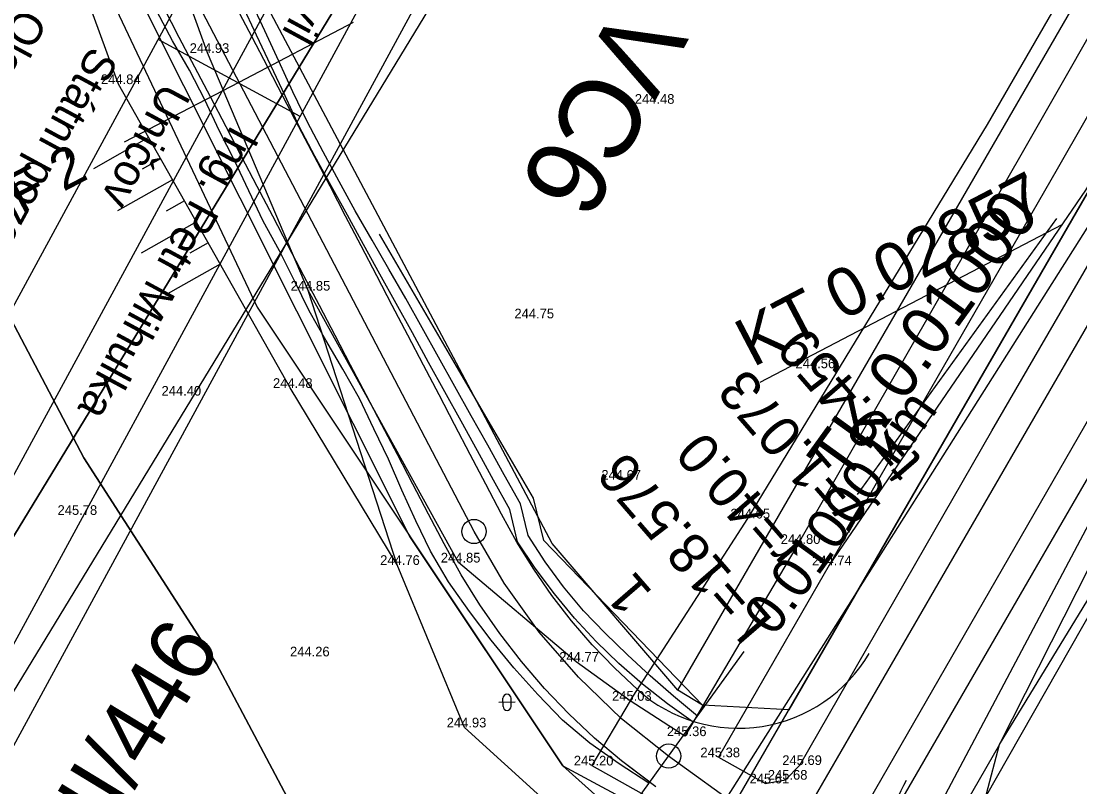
# Model space of a CAD drawing. Extents: x -555887 to -552101, y -1100251 to -1096546.
# Drawn here: x -554080.2 to -554014.6, y -1097317.8 to -1097270.3 of the extents above; entities that cross this region are included whole.
import ezdxf

# ---------------------------------------------------------------- set-up
doc = ezdxf.new("R2010")
doc.units = 0
for name, color, linetype in [('PARCELY_cesty', 7, 'Continuous'), ('PARCELY_silnice', 7, 'Continuous'), ('PARCELY_VHO', 7, 'Continuous'), ('POLYGONY_rozšíření', 7, 'Continuous'), ('POLYGONY_SITUACE_PF', 7, 'Continuous'), ('POLYGONY_SITUACE_PF_POPISY', 7, 'Continuous'), ('POLYGONY_SITUACE_PO', 7, 'Continuous'), ('ROZHLED_parcela_cesty', 7, 'Continuous'), ('ROZHLED_ram_legenda_1', 7, 'Continuous'), ('ROZHLED_ram_legenda_2', 7, 'Continuous'), ('ROZHLED_trojuhelniky_1', 7, 'Continuous'), ('ROZHLED_trojuhelniky_2', 7, 'Continuous'), ('Výškopis', 7, 'Continuous'), ('ZSST', 7, 'Continuous'), ('zájem', 7, 'Continuous')]:
    doc.layers.add(name, color=color, linetype=linetype)

msp = doc.modelspace()

# ---------------------------------------------------------------- linework, layer by layer
for p, q in [((-554034.416, -1097292.667), (-554015.721, -1097282.901)), ((-554028.391, -1097299.626), (-554016.05, -1097282.521))]:
    msp.add_line(p, q)
at = {"layer": 'PARCELY_cesty'}
for points in [[(-554039.52, -1097311.76), (-554047.31, -1097302.68), (-554067.59, -1097264.38), (-554070.02, -1097259.26), (-554071.42, -1097254.1), (-554072.18, -1097247.42), (-554073.837, -1097234.701), (-554074.64, -1097229.027), (-554076.858, -1097220.767), (-554079.626, -1097213.575), (-554082.86, -1097207.774), (-554099.501, -1097180.734), (-554106.075, -1097169.208), (-554111.955, -1097157.47), (-554115.449, -1097149.447), (-554124.686, -1097127.011)], [(-554038.74, -1097323.54), (-554046.65, -1097316.45), (-554056.115, -1097302.24), (-554073.622, -1097267.292), (-554075.994, -1097261.695), (-554077.187, -1097257.67), (-554078.248, -1097251.684), (-554079.797, -1097235.406), (-554080.53, -1097230.23), (-554082.571, -1097222.628), (-554085.074, -1097216.125), (-554088.037, -1097210.809), (-554104.663, -1097183.794), (-554111.367, -1097172.04), (-554117.392, -1097160.013), (-554120.974, -1097151.787), (-554130.309, -1097129.113)]]:
    msp.add_lwpolyline(points, dxfattribs=at)
at = {"layer": 'PARCELY_silnice'}
for points in [[(-553861.3, -1097003.46), (-553858.48, -1097005.9), (-553845.75, -1096975.04), (-553836.44, -1096945.29), (-553831.55, -1096945.97), (-553834.33, -1096958.81), (-553843.04, -1096981.51), (-553856.4, -1097007.66), (-554032.65, -1097312.99), (-554038, -1097312.7), (-554039.52, -1097311.76)], [(-553831.55, -1096945.97), (-553822.14, -1096946.52), (-553820.19, -1096947.25), (-553823.19, -1096962.08), (-553832.13, -1096986.8), (-553848.04, -1097015.24), (-554028.81, -1097333.03), (-554038.74, -1097323.54), (-553856.4, -1097007.66), (-553843.04, -1096981.51), (-553834.33, -1096958.81)]]:
    msp.add_lwpolyline(points, close=True, dxfattribs=at)
at = {"layer": 'PARCELY_VHO'}
for points in [[(-553890.36, -1097670.23), (-553902.88, -1097642.35), (-553905.32, -1097611.67), (-553898.3, -1097524.98), (-553901.53, -1097506.94), (-553991.85, -1097382.83), (-554027.72, -1097360.75), (-554038.93, -1097345.45), (-554044.87, -1097337.64), (-554055.91, -1097333.12), (-554068.1, -1097310.12), (-554076.3, -1097297.37), (-554083.64, -1097283.44), (-554094.93, -1097256.14), (-554100.02, -1097244.94), (-554114.01, -1097204.34), (-554130.46, -1097180.06), (-554159.17, -1097101.34)], [(-554141.5, -1097107.04), (-554133.09, -1097133.96), (-554115.31, -1097177.28), (-554094.19, -1097204.11), (-554083.82, -1097222.99), (-554081.04, -1097249.03), (-554076.85, -1097264.17), (-554065.58, -1097288.03), (-554046.65, -1097316.45), (-554038.74, -1097323.54), (-554028.81, -1097333.03), (-554018.781, -1097341.326), (-554015.89, -1097351.24), (-554008.949, -1097355.38), (-553990.01, -1097365.499), (-553983.508, -1097370.361), (-553977.642, -1097376.021), (-553888.1, -1097498.254), (-553882.924, -1097507.258), (-553879.092, -1097522.388), (-553886.84, -1097615.05), (-553883.68, -1097641.57), (-553876.67, -1097669.5)]]:
    msp.add_lwpolyline(points, dxfattribs=at)
at = {"layer": 'POLYGONY_rozšíření'}
for centre, radius, start, end in [((-554035.765, -1097304.731), 9.388, 228.32637, 329.58502), ((-554017.599, -1097321.883), 9, 149.8415, 220.91473)]:
    msp.add_arc(centre, radius, start, end, dxfattribs=at)
at = {"layer": 'POLYGONY_SITUACE_PF'}
for p, q in [((-554066.694, -1097274.074), (-554059.604, -1097270.37)), ((-554073.785, -1097277.778), (-554066.694, -1097274.074)), ((-554040.095, -1097315.845), (-554035.414, -1097309.357)), ((-554044.776, -1097322.332), (-554040.095, -1097315.845))]:
    msp.add_line(p, q, dxfattribs=at)
at = {"layer": 'POLYGONY_SITUACE_PO'}
for p, q in [((-554052.143, -1097301.928), (-554070.907, -1097266.01)), ((-554065.621, -1097271.163), (-554066.506, -1097269.275)), ((-554065.107, -1097270.894), (-554065.979, -1097268.999)), ((-554070.819, -1097271.527), (-554071.782, -1097269.68)), ((-554070.396, -1097271.307), (-554071.361, -1097269.46)), ((-554065.886, -1097271.301), (-554066.851, -1097269.455)), ((-554064.735, -1097273.05), (-554065.621, -1097271.163)), ((-554064.235, -1097272.789), (-554065.107, -1097270.894)), ((-554069.767, -1097273.328), (-554070.819, -1097271.527)), ((-554069.432, -1097273.153), (-554070.396, -1097271.307)), ((-554064.922, -1097273.148), (-554065.886, -1097271.301)), ((-554068.467, -1097275), (-554069.432, -1097273.153)), ((-554063.957, -1097274.994), (-554064.922, -1097273.148)), ((-554063.85, -1097274.938), (-554064.735, -1097273.05)), ((-554063.358, -1097274.681), (-554064.235, -1097272.789)), ((-554068.816, -1097275.182), (-554069.767, -1097273.328)), ((-554067.926, -1097277.068), (-554068.816, -1097275.182)), ((-554067.502, -1097276.846), (-554068.467, -1097275)), ((-554062.992, -1097276.841), (-554063.957, -1097274.994)), ((-554062.964, -1097276.826), (-554063.85, -1097274.938)), ((-554062.458, -1097276.562), (-554063.358, -1097274.681)), ((-554066.983, -1097278.926), (-554067.926, -1097277.068)), ((-554066.538, -1097278.693), (-554067.502, -1097276.846)), ((-554062.028, -1097278.687), (-554062.992, -1097276.841)), ((-554062.001, -1097278.673), (-554062.964, -1097276.826)), ((-554061.494, -1097278.408), (-554062.458, -1097276.562)), ((-554060.486, -1097280.232), (-554061.494, -1097278.408)), ((-554066.086, -1097280.808), (-554066.983, -1097278.926)), ((-554065.573, -1097280.539), (-554066.538, -1097278.693)), ((-554061.063, -1097280.534), (-554062.028, -1097278.687)), ((-554060.994, -1097280.498), (-554062.001, -1097278.673)), ((-554059.495, -1097282.065), (-554060.486, -1097280.232)), ((-554065.211, -1097282.701), (-554066.086, -1097280.808)), ((-554064.608, -1097282.386), (-554065.573, -1097280.539)), ((-554060.098, -1097282.38), (-554061.063, -1097280.534)), ((-554059.988, -1097282.323), (-554060.994, -1097280.498)), ((-554063.644, -1097284.233), (-554064.608, -1097282.386)), ((-554059.134, -1097284.227), (-554060.098, -1097282.38)), ((-554058.981, -1097284.147), (-554059.988, -1097282.323)), ((-554058.447, -1097283.868), (-554059.495, -1097282.065)), ((-554064.201, -1097284.524), (-554065.211, -1097282.701)), ((-554062.679, -1097286.079), (-554063.644, -1097284.233)), ((-554058.169, -1097286.074), (-554059.134, -1097284.227)), ((-554057.975, -1097285.972), (-554058.981, -1097284.147)), ((-554057.412, -1097285.678), (-554058.447, -1097283.868)), ((-554063.271, -1097286.388), (-554064.201, -1097284.524)), ((-554056.377, -1097287.488), (-554057.412, -1097285.678)), ((-554061.715, -1097287.926), (-554062.679, -1097286.079)), ((-554057.205, -1097287.92), (-554058.169, -1097286.074)), ((-554056.969, -1097287.797), (-554057.975, -1097285.972)), ((-554062.358, -1097288.262), (-554063.271, -1097286.388)), ((-554055.353, -1097289.303), (-554056.377, -1097287.488)), ((-554061.312, -1097290.066), (-554062.358, -1097288.262)), ((-554060.75, -1097289.772), (-554061.715, -1097287.926)), ((-554056.24, -1097289.767), (-554057.205, -1097287.92)), ((-554055.962, -1097289.622), (-554056.969, -1097287.797)), ((-554054.956, -1097291.446), (-554055.962, -1097289.622)), ((-554054.342, -1097291.126), (-554055.353, -1097289.303)), ((-554060.267, -1097291.87), (-554061.312, -1097290.066)), ((-554059.785, -1097291.619), (-554060.75, -1097289.772)), ((-554055.275, -1097291.613), (-554056.24, -1097289.767)), ((-554053.949, -1097293.271), (-554054.956, -1097291.446)), ((-554053.331, -1097292.948), (-554054.342, -1097291.126)), ((-554059.23, -1097293.679), (-554060.267, -1097291.87)), ((-554058.821, -1097293.465), (-554059.785, -1097291.619)), ((-554054.311, -1097293.46), (-554055.275, -1097291.613)), ((-554057.856, -1097295.312), (-554058.821, -1097293.465)), ((-554053.346, -1097295.306), (-554054.311, -1097293.46)), ((-554052.943, -1097295.096), (-554053.949, -1097293.271)), ((-554052.314, -1097294.767), (-554053.331, -1097292.948)), ((-554058.34, -1097295.564), (-554059.23, -1097293.679)), ((-554051.29, -1097296.583), (-554052.314, -1097294.767)), ((-554056.891, -1097297.158), (-554057.856, -1097295.312)), ((-554052.381, -1097297.153), (-554053.346, -1097295.306)), ((-554051.937, -1097296.921), (-554052.943, -1097295.096)), ((-554057.446, -1097297.448), (-554058.34, -1097295.564)), ((-554050.285, -1097298.408), (-554051.29, -1097296.583)), ((-554056.614, -1097299.364), (-554057.446, -1097297.448)), ((-554055.927, -1097299.005), (-554056.891, -1097297.158)), ((-554051.417, -1097298.999), (-554052.381, -1097297.153)), ((-554050.93, -1097298.745), (-554051.937, -1097296.921)), ((-554049.924, -1097300.57), (-554050.93, -1097298.745)), ((-554049.259, -1097300.223), (-554050.285, -1097298.408)), ((-554055.744, -1097301.26), (-554056.614, -1097299.364)), ((-554054.962, -1097300.852), (-554055.927, -1097299.005)), ((-554050.452, -1097300.846), (-554051.417, -1097298.999)), ((-554049.457, -1097302.566), (-554049.924, -1097300.57)), ((-554048.795, -1097302.179), (-554049.259, -1097300.223)), ((-554054.837, -1097303.137), (-554055.744, -1097301.26)), ((-554053.997, -1097302.698), (-554054.962, -1097300.852)), ((-554049.495, -1097302.588), (-554050.452, -1097300.846)), ((-554050.273, -1097305.136), (-554052.143, -1097301.928)), ((-554052.948, -1097304.607), (-554053.997, -1097302.698)), ((-554048.448, -1097304.267), (-554049.495, -1097302.588)), ((-554048.353, -1097304.205), (-554049.457, -1097302.566)), ((-554047.733, -1097303.798), (-554048.795, -1097302.179)), ((-554053.716, -1097305.056), (-554054.837, -1097303.137)), ((-554046.6, -1097305.365), (-554047.733, -1097303.798)), ((-554051.791, -1097306.463), (-554052.948, -1097304.607)), ((-554047.316, -1097305.89), (-554048.448, -1097304.267)), ((-554047.168, -1097305.782), (-554048.353, -1097304.205)), ((-554052.426, -1097306.88), (-554053.716, -1097305.056)), ((-554048.113, -1097308.157), (-554050.273, -1097305.136)), ((-554046.108, -1097307.458), (-554047.316, -1097305.89)), ((-554045.913, -1097307.298), (-554047.168, -1097305.782)), ((-554045.358, -1097306.845), (-554046.6, -1097305.365)), ((-554050.54, -1097308.257), (-554051.791, -1097306.463)), ((-554051.088, -1097308.659), (-554052.426, -1097306.88)), ((-554044.581, -1097308.743), (-554045.913, -1097307.298)), ((-554044.022, -1097308.236), (-554045.358, -1097306.845)), ((-554044.82, -1097308.96), (-554046.108, -1097307.458)), ((-554049.205, -1097309.99), (-554050.54, -1097308.257)), ((-554045.682, -1097310.965), (-554048.113, -1097308.157)), ((-554042.636, -1097309.568), (-554044.022, -1097308.236)), ((-554049.676, -1097310.375), (-554051.088, -1097308.659)), ((-554043.447, -1097310.385), (-554044.82, -1097308.96)), ((-554043.171, -1097310.107), (-554044.581, -1097308.743)), ((-554041.225, -1097310.867), (-554042.636, -1097309.568)), ((-554048.2, -1097312.031), (-554049.676, -1097310.375)), ((-554047.781, -1097311.65), (-554049.205, -1097309.99)), ((-554042.008, -1097311.743), (-554043.447, -1097310.385)), ((-554041.701, -1097311.399), (-554043.171, -1097310.107)), ((-554043.001, -1097313.535), (-554045.682, -1097310.965)), ((-554039.786, -1097312.137), (-554041.225, -1097310.867)), ((-554046.264, -1097313.225), (-554047.781, -1097311.65)), ((-554042.008, -1097311.743), (-554042.008, -1097311.743)), ((-554042.008, -1097311.743), (-554042.008, -1097311.743)), ((-554040.165, -1097312.608), (-554041.701, -1097311.399)), ((-554046.661, -1097313.626), (-554048.2, -1097312.031)), ((-554038.313, -1097313.375), (-554039.786, -1097312.137)), ((-554044.673, -1097314.726), (-554046.264, -1097313.225)), ((-554038.573, -1097313.736), (-554040.165, -1097312.608)), ((-554044.967, -1097315.056), (-554046.661, -1097313.626)), ((-554040.093, -1097315.846), (-554043.001, -1097313.535)), ((-554043.159, -1097316.332), (-554044.967, -1097315.056)), ((-554043.003, -1097316.139), (-554044.673, -1097314.726)), ((-554043.003, -1097316.139), (-554044.673, -1097314.726)), ((-554031.985, -1097321.695), (-554040.093, -1097315.846)), ((-554041.31, -1097317.528), (-554043.159, -1097316.332)), ((-554041.265, -1097317.466), (-554043.003, -1097316.139)), ((-554040.89, -1097317.753), (-554043.003, -1097316.139))]:
    msp.add_line(p, q, dxfattribs=at)
for centre in [(-554052.143, -1097301.928), (-554040.093, -1097315.846)]:
    msp.add_circle(centre, 0.75, dxfattribs=at)
at = {"layer": 'ROZHLED_parcela_cesty'}
msp.add_lwpolyline([(-554065.58, -1097288.03), (-554046.65, -1097316.45), (-554041.23, -1097319.36), (-554038.83, -1097321.49), (-554038.74, -1097323.54), (-554032.65, -1097312.99), (-554038, -1097312.7), (-554047.82, -1097302.49), (-554048.47, -1097299.87), (-554057.99, -1097283.5)], dxfattribs=at)
at = {"layer": 'ROZHLED_ram_legenda_1'}
for p, q in [((-554063.6, -1097256.492), (-554120.836, -1097361.963)), ((-554059.206, -1097258.877), (-554116.441, -1097364.348)), ((-554062.92, -1097276.204), (-554071.709, -1097271.434))]:
    msp.add_line(p, q, dxfattribs=at)
for points in [[(-554050.744, -1097260.056), (-554139.459, -1097423.536), (-554197.468, -1097392.056), (-554108.752, -1097228.576)], [(-554054.811, -1097261.262), (-554140.665, -1097419.468), (-554193.4, -1097390.85), (-554107.547, -1097232.644)]]:
    msp.add_lwpolyline(points, close=True, dxfattribs=at)
at = {"layer": 'ROZHLED_ram_legenda_2'}
msp.add_lwpolyline([(-553994.764, -1097161.002), (-553815.355, -1097270.146), (-553969.717, -1097523.882), (-554149.126, -1097414.737)], close=True, dxfattribs=at)
msp.add_lwpolyline([(-553994.764, -1097161.002), (-553815.355, -1097270.146), (-553969.717, -1097523.882), (-554149.126, -1097414.737)], close=True, dxfattribs=at)
for points in [[(-554149.126, -1097414.737), (-553969.717, -1097523.882), (-553815.355, -1097270.146), (-553994.764, -1097161.002), (-554149.126, -1097414.737)], [(-553822.226, -1097271.819), (-553971.39, -1097517.011), (-554142.255, -1097413.064), (-553993.091, -1097167.872), (-553822.226, -1097271.819)], [(-553822.226, -1097271.819), (-553971.39, -1097517.011), (-554142.255, -1097413.064), (-553993.091, -1097167.872), (-553822.226, -1097271.819)]]:
    msp.add_lwpolyline(points, dxfattribs=at)
at = {"layer": 'ROZHLED_trojuhelniky_1'}
for p in [(-554036.491, -1097318.429), (-554032.67, -1097321.18)]:
    msp.add_line(p, (-553972.591, -1097217.302), dxfattribs=at)
at = {"layer": 'ROZHLED_trojuhelniky_2'}
for p in [(-554030.46, -1097323.44), (-554027.516, -1097326.853)]:
    msp.add_line(p, (-553970.641, -1097219.412), dxfattribs=at)
at = {"layer": 'ZSST'}
for p, q in [((-554072.294, -1097277.517), (-554075.705, -1097279.446)), ((-554071.556, -1097278.823), (-554072.691, -1097279.465)), ((-554070.817, -1097280.128), (-554074.228, -1097282.057)), ((-554070.079, -1097281.434), (-554071.215, -1097282.076)), ((-554069.34, -1097282.739), (-554072.751, -1097284.669)), ((-554068.602, -1097284.045), (-554069.738, -1097284.688)), ((-554067.863, -1097285.351), (-554071.274, -1097287.28)), ((-554049.598, -1097312.513), (-554050.598, -1097312.518)), ((-554050.347, -1097312.767), (-554050.35, -1097312.267)), ((-554049.847, -1097312.764), (-554049.85, -1097312.264))]:
    msp.add_line(p, q, dxfattribs=at)
for points in [[(-554042.48, -1097312.42), (-554035.18, -1097301.12), (-554020.35, -1097276.71), (-554001.25, -1097243.62), (-553975.55, -1097199.35), (-553927.26, -1097115.35), (-553902.63, -1097072.54), (-553878.35, -1097029.34), (-553858.27, -1096995.26), (-553851.54, -1096982.63), (-553845.34, -1096967.24), (-553838.37, -1096941.91), (-553834.5, -1096923.22)], [(-553831.64, -1096923.82), (-553835.69, -1096943.09), (-553842.4, -1096966.86), (-553850.34, -1096985.69), (-553856.05, -1096996.17), (-553876.09, -1097031.09), (-553900.82, -1097073.95), (-553925.65, -1097117.01), (-553973.36, -1097200.46), (-553998.81, -1097244.48), (-554018.03, -1097278.18), (-554032.06, -1097302.7), (-554039.09, -1097314.61), (-554042.48, -1097312.42), (-554044.85, -1097316.43), (-554041.28, -1097318.43), (-554043.66, -1097322.75), (-554050.44, -1097334.64), (-554051.91, -1097337.2)], [(-553818.18, -1096926.71), (-553821.78, -1096945.09), (-553822.5, -1096948.29), (-553824.54, -1096956.94), (-553827.64, -1096967.4), (-553833.07, -1096981.13), (-553839.89, -1096995.89), (-553855.52, -1097024.97), (-553869.86, -1097050.06), (-553885.29, -1097076.39), (-553900.2, -1097101.88), (-553913.69, -1097125.22), (-553931.8, -1097156.33), (-553935.29, -1097162.25), (-553959.78, -1097204.54), (-553977.15, -1097234.71), (-553995.37, -1097266.5), (-554014.37, -1097299.01), (-554027.49, -1097321.67), (-554032.14, -1097329.71), (-554046.52, -1097353.89)], [(-554056.9, -1097304), (-554063.52, -1097293.03), (-554074.17, -1097274.2), (-554078.71, -1097261.75), (-554082.34, -1097246.77), (-554082.1, -1097236.17), (-554084.78, -1097223.3), (-554095.29, -1097205.66), (-554110.17, -1097187.25), (-554117, -1097177.37), (-554121.76, -1097162.68), (-554126.27, -1097148.83), (-554134.49, -1097136.49), (-554138.97, -1097119.53)], [(-553924.99, -1097120.68), (-553971.37, -1097201.71), (-553996.85, -1097245.92), (-554016.03, -1097279.48), (-554030.15, -1097304.02), (-554037.01, -1097315.92), (-554034.1, -1097317.54), (-554032.86, -1097317.31), (-554031.97, -1097316.4), (-554020.07, -1097295.69), (-554001.07, -1097262.91), (-553982.69, -1097231.14), (-553965.04, -1097200.55), (-553952.61, -1097179.27), (-553950.84, -1097176.19), (-553920.35, -1097123.26)], [(-554043.64, -1097319), (-554047.77, -1097318.58), (-554052.74, -1097314.07), (-554056.9, -1097304), (-554062.41, -1097287), (-554068.66, -1097272.27), (-554076.19, -1097251.39), (-554079.41, -1097237.5), (-554082.27, -1097222.72), (-554086.75, -1097212.07), (-554091.28, -1097204.32), (-554100.2, -1097193.1), (-554110.38, -1097176.19), (-554116.77, -1097164.16), (-554127.72, -1097139.75), (-554132.59, -1097127.58)], [(-554019.6, -1097315.12), (-554012.38, -1097300.85), (-553995.46, -1097270.6), (-553983.87, -1097250.35), (-553971.79, -1097229.88), (-553973.03, -1097229.25)], [(-553994.38, -1097247.36), (-554014.28, -1097280.78), (-554030.15, -1097304.02)], [(-554017.87, -1097337.24), (-554021.88, -1097329.21), (-554022.01, -1097324.3), (-554019.6, -1097315.12), (-554011.11, -1097301.23), (-554007.55, -1097295.64), (-553993.46, -1097272.56), (-553972.08, -1097281.03), (-553917.98, -1097299.93), (-553859.38, -1097321.17), (-553801.93, -1097342.05)], [(-554042.48, -1097312.42), (-554045.82, -1097310), (-554053.11, -1097303.85), (-554062.41, -1097287)], [(-554019.6, -1097315.12), (-554024.17, -1097323.07), (-554021.88, -1097329.21)]]:
    msp.add_lwpolyline(points, dxfattribs=at)
for centre, start, end in [((-554050.1, -1097312.265), 0.28648, 180.28648), ((-554050.097, -1097312.765), 180.28648, 0.28648)]:
    msp.add_arc(centre, 0.25, start, end, dxfattribs=at)
at = {"layer": 'zájem'}
for points in [[(-554209.05, -1097338.04), (-554121.59, -1097427.95), (-554119.85, -1097429.74), (-554117.62, -1097427.68), (-554074.61, -1097473), (-554067.74, -1097480.24), (-554074.25, -1097435.16), (-554074.7, -1097411.2), (-554072.86, -1097396.87), (-554069.61, -1097384.37), (-554062.54, -1097368.79), (-554059.66, -1097363.67), (-554044.87, -1097337.64), (-554055.91, -1097333.12), (-554068.1, -1097310.12), (-554076.3, -1097297.37), (-554083.64, -1097283.44), (-554094.93, -1097256.14), (-554100.02, -1097244.94), (-554114.01, -1097204.34), (-554130.46, -1097180.06), (-554159.17, -1097101.34)], [(-554159.17, -1097101.34), (-554130.46, -1097180.06), (-554114.01, -1097204.34), (-554100.02, -1097244.94), (-554094.93, -1097256.14), (-554083.64, -1097283.44), (-554076.3, -1097297.37), (-554068.1, -1097310.12), (-554055.91, -1097333.12), (-554044.87, -1097337.64), (-554059.66, -1097363.67), (-554062.54, -1097368.79), (-554069.61, -1097384.37), (-554072.86, -1097396.87), (-554074.7, -1097411.2), (-554074.25, -1097435.16), (-554067.74, -1097480.24), (-554074.61, -1097473), (-554117.62, -1097427.68), (-554119.85, -1097429.74), (-554121.59, -1097427.95), (-554209.05, -1097338.04)]]:
    msp.add_lwpolyline(points, dxfattribs=at)

# ---------------------------------------------------------------- texts
for s, height, rotation, p in [('KT 0.02857', 3, 27.58246, (-554034.879, -1097291.781)), ('TK 0.01000', 3, 54.19051, (-554029.202, -1097299.041)), ('t=9.459', 2.5, 130.88648, (-554024.279, -1097297.558)), ('y=1.073', 2.5, 130.88648, (-554027.454, -1097300.765)), ('r=40.0', 2.5, 130.88648, (-554031.636, -1097302.809)), ('L=18.576', 2.5, 130.88648, (-554033.566, -1097307.456)), ('1', 2.5, 130.88648, (-554041.021, -1097305.72))]:
    msp.add_text(s, height=height, rotation=rotation).set_placement(p)
at = {"layer": 'POLYGONY_SITUACE_PF_POPISY'}
for s, rotation, p in [('PF 2', 27.58246, (-554082.186, -1097283.295)), ('0.01000 km', 54.18791, (-554033.577, -1097308.521)), ('PF 1', 220.90993, (-554012.488, -1097316.709))]:
    msp.add_text(s, height=2.5, rotation=rotation, dxfattribs=at).set_placement(p)
at = {"layer": 'ROZHLED_ram_legenda_1'}
for s, height, rotation, p in [('Vyhotovil', 2, 241.51269, (-554058.9, -1097261.459)), ('Olomoucký kraj, Pobočka Olomouc', 2, 241.51269, (-554080.269, -1097269.387)), ('VC6', 5, 241.51256, (-554043.215, -1097268.987)), ('Státní pozemkový úřad, Krajský pozemkový úřad pro', 2, 241.51269, (-554075.872, -1097271.769)), ('Uničov', 2, 241.51269, (-554071.403, -1097274.016)), ('Ing. Petr Mihulka', 2, 241.51269, (-554067.15, -1097276.661))]:
    msp.add_text(s, height=height, rotation=rotation, dxfattribs=at).set_placement(p)
at = {"layer": 'ROZHLED_ram_legenda_2'}
msp.add_text('Rozhledové poměry - napojení DC4 na  silnici II/446', height=4, rotation=58.6856, dxfattribs=at).set_placement((-554131.926, -1097414.479))
at = {"layer": 'Výškopis'}
for s, p in [('244.93', (-554069.754, -1097272.27)), ('244.84', (-554075.247, -1097274.2)), ('244.48', (-554042.185, -1097275.42)), ('244.85', (-554063.5, -1097287)), ('244.75', (-554049.641, -1097288.72)), ('244.56', (-554032.233, -1097291.81)), ('244.40', (-554071.497, -1097293.51)), ('244.48', (-554064.595, -1097293.03)), ('244.67', (-554044.257, -1097298.72)), ('245.78', (-554077.937, -1097300.9)), ('244.65', (-554036.263, -1097301.12)), ('244.80', (-554033.145, -1097302.7)), ('244.76', (-554057.957, -1097304)), ('244.85', (-554054.2, -1097303.85)), ('244.74', (-554031.207, -1097304.02)), ('244.26', (-554063.54, -1097309.67)), ('244.77', (-554046.865, -1097310)), ('245.03', (-554043.596, -1097312.42)), ('244.93', (-554053.834, -1097314.07)), ('245.36', (-554040.198, -1097314.61)), ('245.20', (-554045.962, -1097316.43)), ('245.38', (-554038.124, -1097315.92)), ('245.69', (-554033.053, -1097316.4)), ('245.61', (-554035.08, -1097317.54)), ('245.68', (-554033.948, -1097317.31))]:
    msp.add_text(s, height=0.6, dxfattribs=at).set_placement(p)

doc.saveas('drawing.dxf')
